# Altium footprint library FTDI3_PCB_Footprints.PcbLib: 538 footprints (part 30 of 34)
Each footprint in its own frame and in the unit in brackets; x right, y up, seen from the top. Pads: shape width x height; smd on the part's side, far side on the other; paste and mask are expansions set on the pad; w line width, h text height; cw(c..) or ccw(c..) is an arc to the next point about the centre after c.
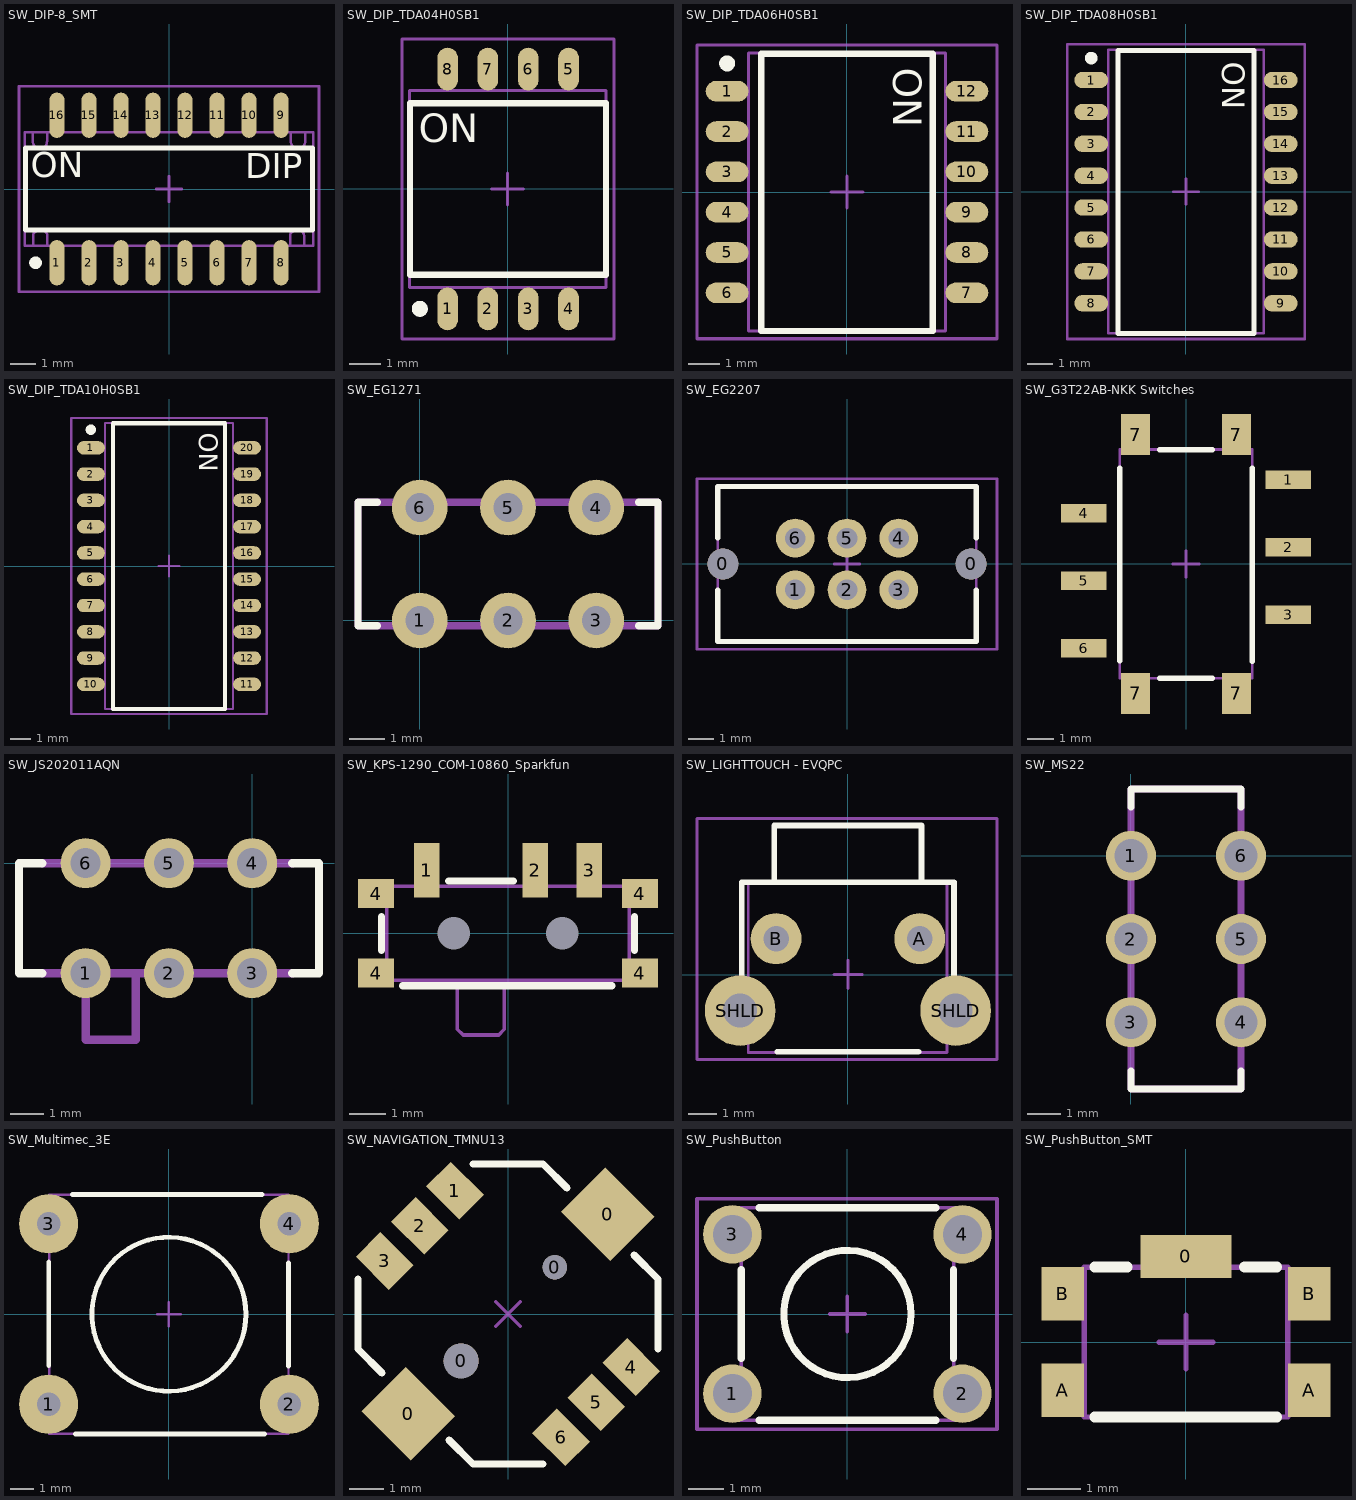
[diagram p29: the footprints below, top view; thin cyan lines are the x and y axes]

## SW_DIP-8_SMT [mm] "DIP Switch; SMT"
height 1.5
pads (16):
  oval 0.6x1.8 smd: 1(-4.445,-2.925) 2(-3.175,-2.925) 3(-1.905,-2.925) 4(-0.635,-2.925) 5(0.635,-2.925) 6(1.905,-2.925) 7(3.175,-2.925) 8(4.445,-2.925) 9(4.445,2.925) 10(3.175,2.925) 11(1.905,2.925) 12(0.635,2.925) 13(-0.635,2.925) 14(-1.905,2.925) 15(-3.175,2.925) 16(-4.445,2.925)
Top Overlay:
  circle w0.25: c-5.295,-2.925 r0.125
  lines w0.2: -5.7,-1.625 5.7,-1.625 5.7,1.625 -5.7,1.625 -5.7,-1.625
  text "ON" at -5.477,0.466 h1
  text "DIP" at 3.022,0.423 h1
M13_Assembly_Info:
  lines w0.1: -5.404,2.249 -5.404,1.892 ccw(c-5.12,1.892) -4.836,1.892 -4.836,2.25 ; -5.391,-2.25 -5.391,-1.892 cw(c-5.107,-1.892) -4.823,-1.892 -4.823,-2.249 ; 4.801,-2.25 4.801,-1.892 cw(c5.085,-1.892) 5.369,-1.892 5.369,-2.249 ; 4.831,2.249 4.831,1.892 ccw(c5.115,1.892) 5.399,1.892 5.399,2.25 ; -5.725,-2.25 5.725,-2.25 5.725,2.25 -5.725,2.25 -5.725,-2.25
M15_Country_Yard:
  lines w0.1: -0.5,0 0.5,0 ; 0,-0.5 0,0.5 ; -5.95,-4.075 5.95,-4.075 5.95,4.075 -5.95,4.075 -5.95,-4.075
3D body: height 1.5, standoff 0.1, extent -5.725,-2.25 5.725,2.25

## SW_DIP_TDA04H0SB1 [mm] "DIP Switch; Half pitch (1.27mm); 4 possitions; C&K; TDA04H0SB1"
height 2.3
pads (8):
  oval 0.65x1.35 smd: 1(-1.89,-3.775) 2(-0.62,-3.775) 3(0.65,-3.775) 4(1.92,-3.775) 5(1.92,3.775) 6(0.65,3.775) 7(-0.62,3.775) 8(-1.89,3.775)
Top Overlay:
  circle w0.25: c-2.765,-3.775 r0.125
  lines w0.2: -3.075,-2.7 3.1,-2.7 3.1,2.7 -3.075,2.7 -3.075,-2.7
  text "ON" at -2.8,1.475 h0.9
M13_Assembly_Info:
  lines w0.1: -3.09,-3.1 3.1,-3.1 3.1,3.1 -3.09,3.1 -3.09,-3.1
M15_Country_Yard:
  lines w0.1: -0.5,0 0.5,0 ; 0,-0.5 0,0.5 ; -3.325,-4.725 3.35,-4.725 3.35,4.725 -3.325,4.725 -3.325,-4.725
3D body: height 2.3, standoff 1.9, extent 1.625,-0.7 2.225,0
3D body: height 2, standoff 1.3, extent 1.625,0 2.225,0.7
3D body: height 2.3, standoff 1.9, extent 0.35,-0.7 0.95,0
3D body: height 2, standoff 1.3, extent 0.35,0 0.95,0.7
3D body: height 2.3, standoff 1.9, extent -0.925,-0.7 -0.325,0
3D body: height 2, standoff 1.3, extent -0.925,0 -0.325,0.7
3D body: height 2, standoff 1.3, extent -2.2,0 -1.6,0.7
3D body: height 2.3, standoff 1.9, extent -2.2,-0.7 -1.6,0
3D body: height 2.3, standoff 1.9, extent -3.1,-3.1 3.1,-2
3D body: height 2.3, standoff 1.9, extent -3.1,2 3.1,3.1
3D body: height 1.9, standoff 0.1, extent -3.1,-3.1 3.09,3.1
3D body: height 0.15, standoff 0, extent 1.7,3.5 2.15,4.1
3D body: height 0.55, standoff 0, extent 1.7,3.35 2.15,3.5
3D body: height 0.55, standoff 0.4, extent 1.7,2.95 2.15,3.35
3D body: height 0.55, standoff 0.4, extent 0.425,2.95 0.875,3.35
3D body: height 0.55, standoff 0, extent 0.425,3.35 0.875,3.5
3D body: height 0.15, standoff 0, extent 0.425,3.5 0.875,4.1
3D body: height 0.55, standoff 0.4, extent -0.85,2.95 -0.4,3.35
3D body: height 0.55, standoff 0, extent -0.85,3.35 -0.4,3.5
3D body: height 0.15, standoff 0, extent -0.85,3.5 -0.4,4.1
3D body: height 0.55, standoff 0.4, extent -2.125,2.95 -1.675,3.35
3D body: height 0.55, standoff 0, extent -2.125,3.35 -1.675,3.5
3D body: height 0.15, standoff 0, extent -2.125,3.5 -1.675,4.1
3D body: height 0.55, standoff 0.4, extent -2.1,-3.35 -1.65,-2.95
3D body: height 0.55, standoff 0, extent -2.1,-3.5 -1.65,-3.35
3D body: height 0.15, standoff 0, extent -2.1,-4.1 -1.65,-3.5
3D body: height 0.55, standoff 0.4, extent -0.85,-3.35 -0.4,-2.95
3D body: height 0.55, standoff 0, extent -0.85,-3.5 -0.4,-3.35
3D body: height 0.15, standoff 0, extent -0.85,-4.1 -0.4,-3.5
3D body: height 0.55, standoff 0.4, extent 0.425,-3.35 0.875,-2.95
3D body: height 0.55, standoff 0, extent 0.425,-3.5 0.875,-3.35
3D body: height 0.15, standoff 0, extent 0.425,-4.1 0.875,-3.5
3D body: height 0.55, standoff 0.4, extent 1.7,-3.35 2.15,-2.95
3D body: height 0.55, standoff 0, extent 1.7,-3.5 2.15,-3.35
3D body: height 0.15, standoff 0, extent 1.7,-4.1 2.15,-3.5

## SW_DIP_TDA06H0SB1 [mm] "DIP Switch; Half pitch (1.27mm); 6 possitions; C&K; TDA06H0SB1"
height 2.3
pads (12):
  oval 1.35x0.65 smd: 1(-3.775,3.175) 2(-3.775,1.905) 3(-3.775,0.635) 4(-3.775,-0.635) 5(-3.775,-1.905) 6(-3.775,-3.175) 7(3.775,-3.175) 8(3.775,-1.905) 9(3.775,-0.635) 10(3.775,0.635) 11(3.775,1.905) 12(3.775,3.175)
Top Overlay:
  circle w0.25: c-3.775,4.05 r0.125
  lines w0.2: -2.7,-4.38 -2.7,4.36 2.7,4.36 2.7,-4.38 -2.7,-4.38
  text "ON" at 1.45,3.91 h0.9
M13_Assembly_Info:
  lines w0.1: -3.1,-4.38 -3.1,4.375 3.1,4.375 3.1,-4.38 -3.1,-4.38
M15_Country_Yard:
  lines w0.1: -0.5,0 0.5,0 ; 0,-0.5 0,0.5 ; -4.725,-4.62 -4.725,4.63 4.725,4.63 4.725,-4.62 -4.725,-4.62
3D body: height 2.3, standoff 0.1, extent -3.1,-4.37 3.1,4.375

## SW_DIP_TDA08H0SB1 [mm] "DIP Switch; Half pitch (1.27mm); 8 possitions; C&K; TDA08H0SB1"
height 2.3
pads (16):
  oval 1.35x0.65 smd: 1(-3.775,4.445) 2(-3.775,3.175) 3(-3.775,1.905) 4(-3.775,0.635) 5(-3.775,-0.635) 6(-3.775,-1.905) 7(-3.775,-3.175) 8(-3.775,-4.445) 9(3.775,-4.445) 10(3.775,-3.175) 11(3.775,-1.905) 12(3.775,-0.635) 13(3.775,0.635) 14(3.775,1.905) 15(3.775,3.175) 16(3.775,4.445)
Top Overlay:
  circle w0.25: c-3.775,5.32 r0.125
  lines w0.2: -2.7,-5.645 -2.7,5.63 2.7,5.63 2.7,-5.645 -2.7,-5.645
  text "ON" at 1.45,5.18 h0.9
M13_Assembly_Info:
  lines w0.1: -3.1,-5.645 -3.1,5.645 3.1,5.645 3.1,-5.645 -3.1,-5.645
M15_Country_Yard:
  lines w0.1: -0.5,0.005 0.5,0.005 ; 0,-0.495 0,0.505 ; -4.725,-5.87 -4.725,5.88 4.725,5.88 4.725,-5.87 -4.725,-5.87
3D body: height 2.3, standoff 0.1, extent -3.1,-5.645 3.1,5.645

## SW_DIP_TDA10H0SB1 [mm] "DIP Switch; Half pitch (1.27mm); 10 possitions; C&K; TDA10H0SB1"
height 2.3
pads (20):
  oval 1.35x0.65 smd: 1(-3.775,5.715) 2(-3.775,4.445) 3(-3.775,3.175) 4(-3.775,1.905) 5(-3.775,0.635) 6(-3.775,-0.635) 7(-3.775,-1.905) 8(-3.775,-3.175) 9(-3.775,-4.445) 10(-3.775,-5.715) 11(3.775,-5.715) 12(3.775,-4.445) 13(3.775,-3.175) 14(3.775,-1.905) 15(3.775,-0.635) 16(3.775,0.635) 17(3.775,1.905) 18(3.775,3.175) 19(3.775,4.445) 20(3.775,5.715)
Top Overlay:
  circle w0.25: c-3.775,6.59 r0.125
  lines w0.2: -2.7,-6.9 2.7,-6.9 2.7,6.9 -2.7,6.9 -2.7,-6.9
  text "ON" at 1.45,6.45 h0.9
M13_Assembly_Info:
  lines w0.1: -3.1,-6.915 3.1,-6.915 3.1,6.915 -3.1,6.915 -3.1,-6.915
M15_Country_Yard:
  lines w0.1: -0.5,0 0.5,0 ; 0,-0.5 0,0.5 ; -4.725,-7.15 4.725,-7.15 4.725,7.15 -4.725,7.15 -4.725,-7.15
3D body: height 2.3, standoff 0.1, extent -3.1,-6.915 3.1,6.915

## SW_EG1271 [mm] "Switch; SPDT; E Switch EG1271A"
pads (6):
  round 1.575 hole 0.813: 1(0,0) 2(2.5,0) 3(5,0) 4(5,3.2) 5(2.5,3.2) 6(0,3.2)
Top Overlay:
  lines w0.2: -1.2,-0.15 -1.75,-0.15 -1.75,3.35 -1.2,3.35 ; 6.2,-0.15 6.75,-0.15 6.75,3.35 6.2,3.35
M13_Assembly_Info:
  lines w0.2: -1.75,-0.15 -1.75,3.35 6.75,3.35 6.75,-0.15 -1.75,-0.15

## SW_EG2207 [mm] "Switch; SPDT; E Switch EG2207"
pads (8):
  round 1.2 hole 1.2 unplated: 0(-4.8,0) 0(4.8,0)
  round 1.5 hole 0.8: 1(-2,-1) 2(0,-1) 3(2,-1) 4(2,1) 5(0,1) 6(-2,1)
Top Overlay:
  lines w0.2: -5,-1 -5,-3 5,-3 5,-1 ; -5,1 -5,3 5,3 5,1
M13_Assembly_Info:
  lines w0.1: -5,-3 -5,3 5,3 5,-3 -5,-3
M15_Country_Yard:
  lines w0.1: -0.5,0 0.5,0 ; 0,-0.5 0,0.5 ; -5.8,-3.3 5.8,-3.3 5.8,3.3 -5.8,3.3 -5.8,-3.3

## SW_G3T22AB-NKK Switches [mm] "Switch; DPDT; Process Sealed Ultra-Miniature SMT Toggle Switch"
height 9
pads (10):
  rect 1.7x0.7 smd: 1(3.85,3.175) 2(3.85,0.635) 3(3.85,-1.905) 4(-3.85,1.905) 5(-3.85,-0.635) 6(-3.85,-3.175)
  rect 1.1x1.55 smd: 7(-1.9,-4.875) 7(-1.9,4.875) 7(1.9,-4.875) 7(1.9,4.875)
Top Overlay:
  lines w0.2: -2.5,-3.64 -2.5,3.61 ; -1,-4.3 1,-4.3 ; -1,4.3 1,4.3 ; 2.5,-3.67 2.5,3.61
M13_Assembly_Info:
  lines w0.1: -2.5,-4.3 -2.5,4.31 2.5,4.31 2.5,-4.3 -2.5,-4.3
M15_Country_Yard:
  lines w0.1: -0.5,0 0.5,0 ; 0,-0.5 0,0.5
3D body: height 0, standoff 0, extent -2.5,-4.3 2.52,4.31

## SW_JS202011AQN [mm] "PTH  DPDT SW R/A"
height 3.5
pads (6):
  round 1.5 hole 0.9: 1(-5,-3.3) 2(-2.5,-3.3) 3(0,-3.3) 4(0,0) 5(-2.5,0) 6(-5,0)
Top Overlay:
  lines w0.254: -6.3,-3.3 -7,-3.3 -7,0 -6.3,0 ; 1.2,-3.3 2,-3.3 ; 1.2,0 2,0 ; 2.007,-3.302 2.007,0
M13_Assembly_Info:
  lines w0.254: -6.3,-3.3 1.2,-3.3 ; -6.3,0 -2.794,0 -2.769,-0.025 ; -5,-3.3 -5,-5.3 -3.5,-5.3 -3.5,-3.348 ; -2.769,0 1.2,0

## SW_KPS-1290_COM-10860_Sparkfun [mm] "Surface Mount Right Angle Switch; Sparkfun COM-10860"
height 1.4
pads (9):
  round 0 hole 0.9: 0(-1.5,0) 0(1.5,0)
  rect 0.7x1.5 smd: 1(-2.25,1.75) 2(0.75,1.75) 3(2.25,1.75)
  rect 1x0.8 smd: 4(-3.65,-1.1) 4(-3.65,1.1) 4(3.65,-1.1) 4(3.65,1.1)
Top Overlay:
  lines w0.2: -3.5,-0.47 -3.5,0.47 ; -2.91,-1.45 2.88,-1.45 ; -1.64,1.45 0.15,1.45 ; 3.5,-0.47 3.5,0.47
M13_Assembly_Info:
  lines w0.1: -3.35,-0.9 -3.85,-0.9 -3.85,-1.3 -3.35,-1.3 ; -3.35,0.9 -3.85,0.9 -3.85,1.3 -3.35,1.3 ; -2.45,1.3 -2.45,2.2 -2.05,2.2 -2.05,1.3 ; -1.4,-1.31 -1.4,-2.65 -1.24,-2.81 -0.26,-2.81 -0.1,-2.65 -0.1,-1.31 ; 0.55,1.3 0.55,2.2 0.95,2.2 0.95,1.3 ; 2.05,1.3 2.05,2.2 2.45,2.2 2.45,1.3 ; 3.35,-0.9 3.85,-0.9 3.85,-1.3 3.35,-1.3 ; 3.35,0.9 3.85,0.9 3.85,1.3 3.35,1.3 ; -3.35,-1.3 3.35,-1.3 ; -3.35,-1.3 -3.35,1.3 ; -3.35,1.3 3.35,1.3 ; 3.35,-1.3 3.35,1.3
3D body: height 1.3, standoff 0.1, extent -1.4,-2.81 -0.1,-1.31
3D body: height 1.4, standoff 0, extent -3.35,-1.3 3.35,1.3

## SW_LIGHTTOUCH - EVQPC [mm] "Light Touch Switches"
pads (4):
  round 1.8 hole 0.9: A(2.54,1.275) B(-2.54,1.275)
  round 2.5 hole 1.2: SHLD(-3.81,-1.265) SHLD(3.81,-1.265)
Top Overlay:
  lines w0.2: -3.75,3.275 3.75,3.275 ; -2.6,3.275 -2.6,5.275 2.6,5.275 2.6,3.275
  lines w0.203: -3.75,-0.02 -3.75,3.25 ; -2.5,-2.725 2.5,-2.725 ; 3.75,-0.07 3.75,3.25
M13_Assembly_Info:
  lines w0.1: -3.525,-2.75 3.5,-2.75 3.5,3.25 -3.525,3.25 -3.525,-2.75
M15_Country_Yard:
  lines w0.1: -0.492,0.005 0.508,0.005 ; 0,-0.487 0,0.513 ; -5.334,-3 5.271,-3 5.271,5.529 -5.334,5.529 -5.334,-3
3D body: height 0, standoff 0, extent -3.525,-2.75 3.525,3.248

## SW_MS22 [mm] "Switch; DPDT; Apem; MS22"
height 5.5
pads (6):
  round 1.5 hole 1: 1(0,0) 2(0,-2.5) 3(0,-5) 4(3.3,-5) 5(3.3,-2.5) 6(3.3,0)
Top Overlay:
  lines w0.2: 0,-6.45 0,-7 3.3,-7 3.3,-6.45 ; 0,1.45 0,2 3.3,2 3.3,1.45
M13_Assembly_Info:
  lines w0.2: 0,-7 0,2 3.3,2 3.3,-7 0,-7
3D body: height 5.5, standoff 3.5, extent 0.925,-1.95 2.425,-0.45
3D body: height 3.5, standoff 0, extent 0,-7 3.3,2

## SW_Multimec_3E [mm] "3E series Push-Button Switch; Multimec"
height 10.4
pads (4):
  round 2.5 hole 1: 1(-5.075,-3.8) 2(5.085,-3.8) 3(-5.075,3.82) 4(5.085,3.82)
Top Overlay:
  circle w0.2: c0,0 r3.25
  lines w0.2: -5.075,-2.175 -5.075,2.2 ; -4.075,5.05 3.925,5.05 ; -3.95,-5.05 4.05,-5.05 ; 5.05,-2.2 5.05,2.175
M13_Assembly_Info:
  lines w0.1: -5.05,-5.05 -5.05,5.05 5.05,5.05 5.05,-5.05 -5.05,-5.05
M15_Country_Yard:
  lines w0.1: -0.5,0 0.5,0 ; 0,-0.5 0,0.5
3D body: height 0, standoff 0, extent -5.05,-5.05 5.05,5.05

## SW_NAVIGATION_TMNU13 [mm] "TMHU13 navigation switch (joystick)"
height 5
pads (10):
  rect 2x1.8 smd rot 135: 0(-2.864,-2.864) 0(2.864,2.864)
  round 1 hole 1 unplated: 0(-1.344,-1.344)
  round 0.7 hole 0.7 unplated: 0(1.344,1.344)
  rect 1.35x1 smd rot 135: 1(-1.52,3.536) 2(-2.528,2.528) 3(-3.536,1.52) 4(3.536,-1.52) 5(2.528,-2.528) 6(1.52,-3.536)
Top Overlay:
  lines w0.2: -4.3,1.003 -4.3,-1.003 -3.606,-1.697 ; -1.698,-3.605 -1.004,-4.3 1.004,-4.3 ; -1.003,4.3 1.003,4.3 1.697,3.606 ; 3.606,1.698 4.3,1.004 4.3,-1.004
M15_Country_Yard:
  lines w0.1: -0.354,-0.354 0.354,0.354 ; -0.354,0.354 0.354,-0.354

## SW_PushButton [mm] "Push button switch"
pads (4):
  round 1.651 hole 1.1: 1(-3.25,-2.25) 2(3.25,-2.25) 3(-3.25,2.25) 4(3.25,2.25)
Top Overlay:
  circle w0.2: c0,0 r1.8
  lines w0.203: -3,-1.25 -3,1.25 ; -2.5,-3 2.5,-3 ; -2.5,3 2.5,3 ; 3,-1.25 3,1.25
M13_Assembly_Info:
  lines w0.1: -3,-3 3,-3 3,3 -3,3 -3,-3
M15_Country_Yard:
  lines w0.1: -0.5,0 0.5,0 ; 0,-0.5 0,0.5 ; -4.25,-3.25 4.225,-3.25 4.225,3.25 -4.25,3.25 -4.25,-3.25
3D body: height 0, standoff 0, extent -3,-3 3,3

## SW_PushButton_SMT [mm] "Push button switch"
pads (5):
  rect 1.7x0.8 smd: 0(0,1.599)
  rect 0.8x1 smd: A(-2.301,-0.9) A(2.302,-0.896) B(-2.301,0.901) B(2.302,0.901)
Top Overlay:
  lines w0.2: -1.702,-1.4 1.698,-1.4 ; -1.702,1.401 -1.098,1.401 ; 1.094,1.401 1.698,1.401
M13_Assembly_Info:
  lines w0.1: -1.9,-1.4 1.9,-1.4 1.9,1.4 -1.9,1.4 -1.9,-1.4
M15_Country_Yard:
  lines w0.1: -0.5,-0.002 0.5,-0.002 ; 0,-0.502 0,0.498
3D body: height 1.9, standoff 0, extent -1.9,-1.4 1.9,1.4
